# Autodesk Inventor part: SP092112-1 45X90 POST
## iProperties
Created: 2012-09
Part Number: SP092112-1 45X90 POST
Material: Aluminum-6061
Description: PROFILE 45X90 UL
Document SubType Name: Modeling
Designer: Administrator
Stock Number: 20.1067 PROFILE 45X90 UL
Density: 2.71 g/cm^3
Mass: 5211.69 g
Surface Area: 21120.5 cm^2
Volume: 1923.13 cm^3
FINISH: CLEAR ANODIZED
Author: Administrator
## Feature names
1. Extrusion1
